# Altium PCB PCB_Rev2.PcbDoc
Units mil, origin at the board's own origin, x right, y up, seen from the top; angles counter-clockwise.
Board outline 1399.86 x 1600.52 mil, 2 copper layers (Top Layer, Bottom Layer), stack 61.2 mil thick; 31 components, 28 nets, 195 pads, 54 vias.
Unrouted connection lines stored in the file: 15.
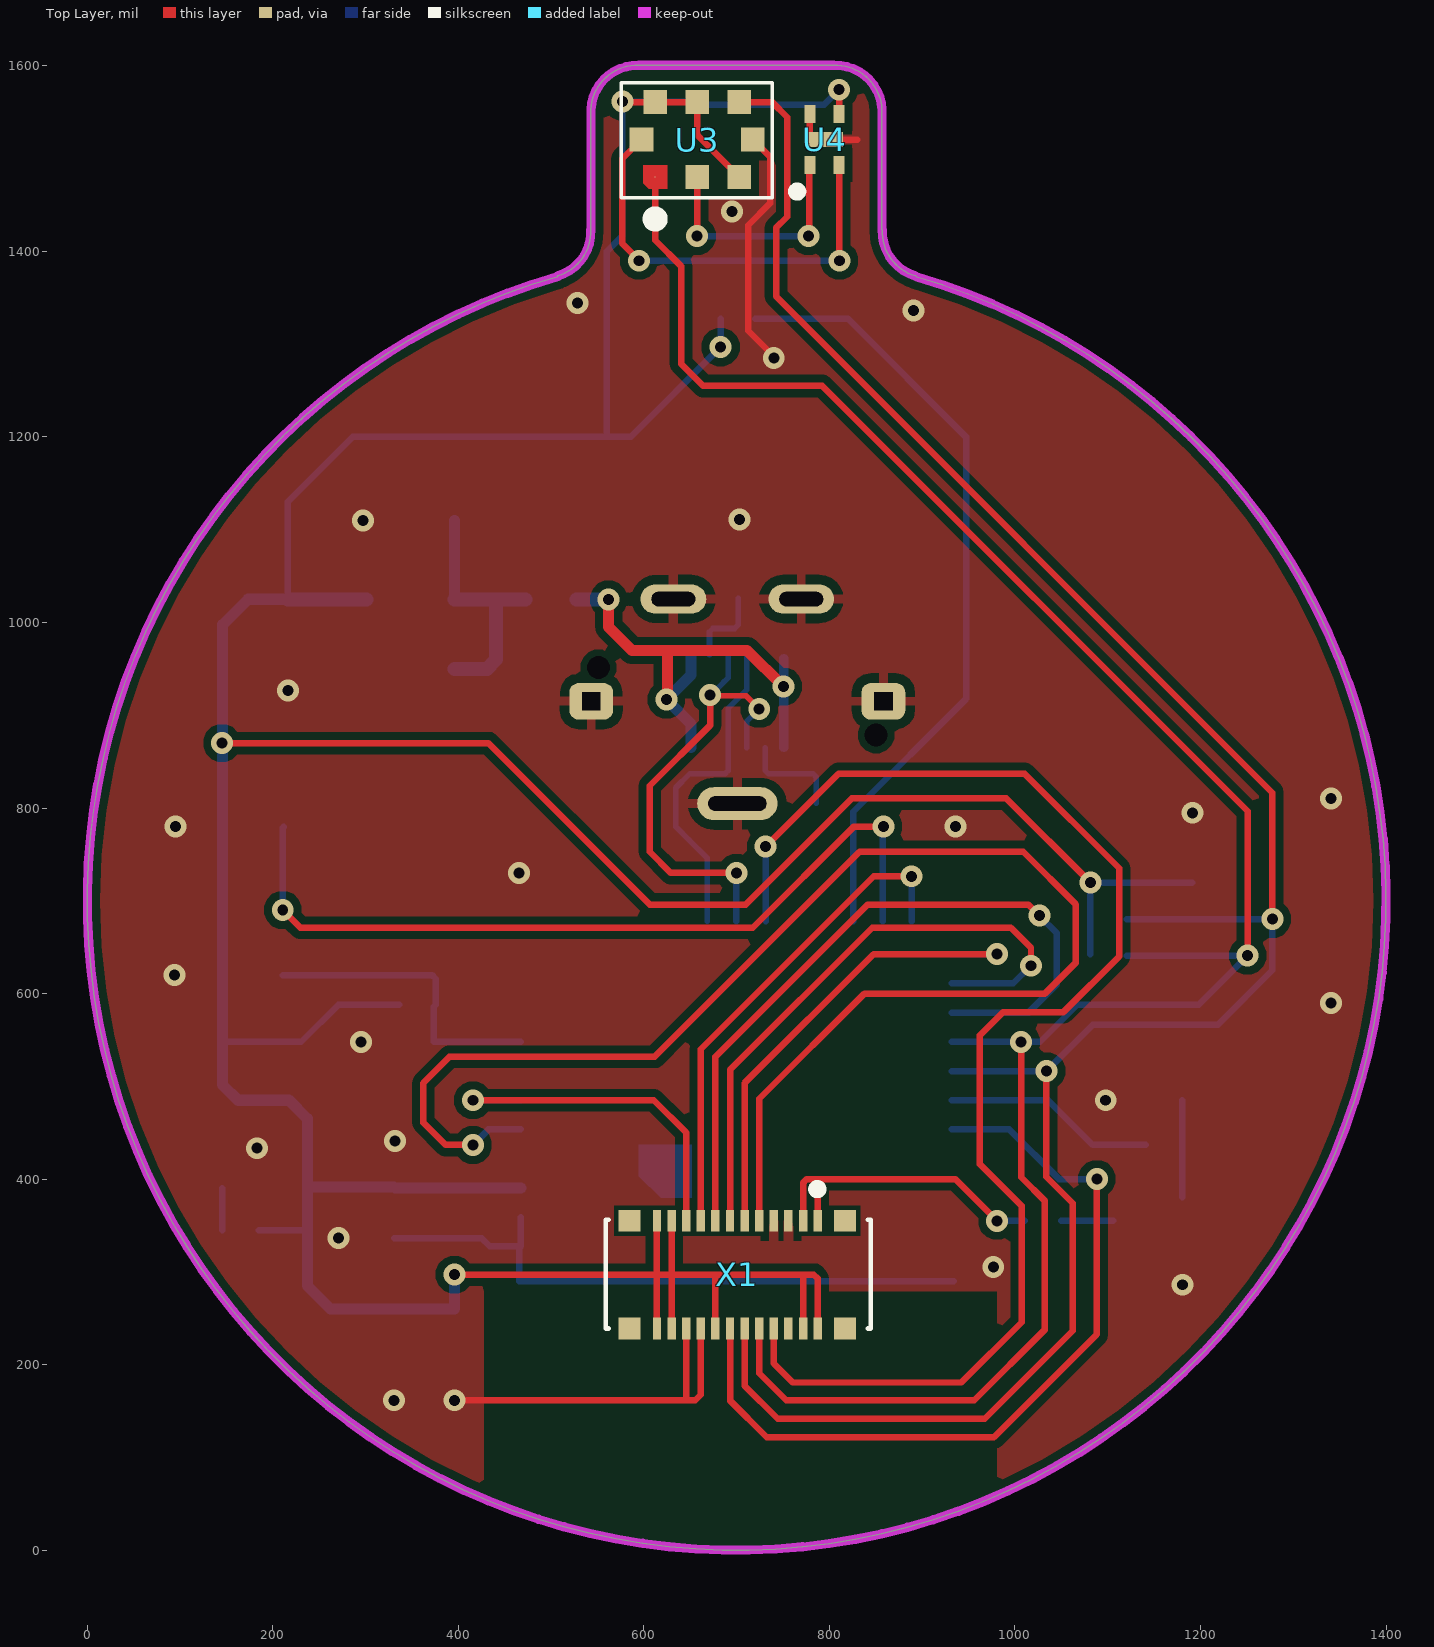
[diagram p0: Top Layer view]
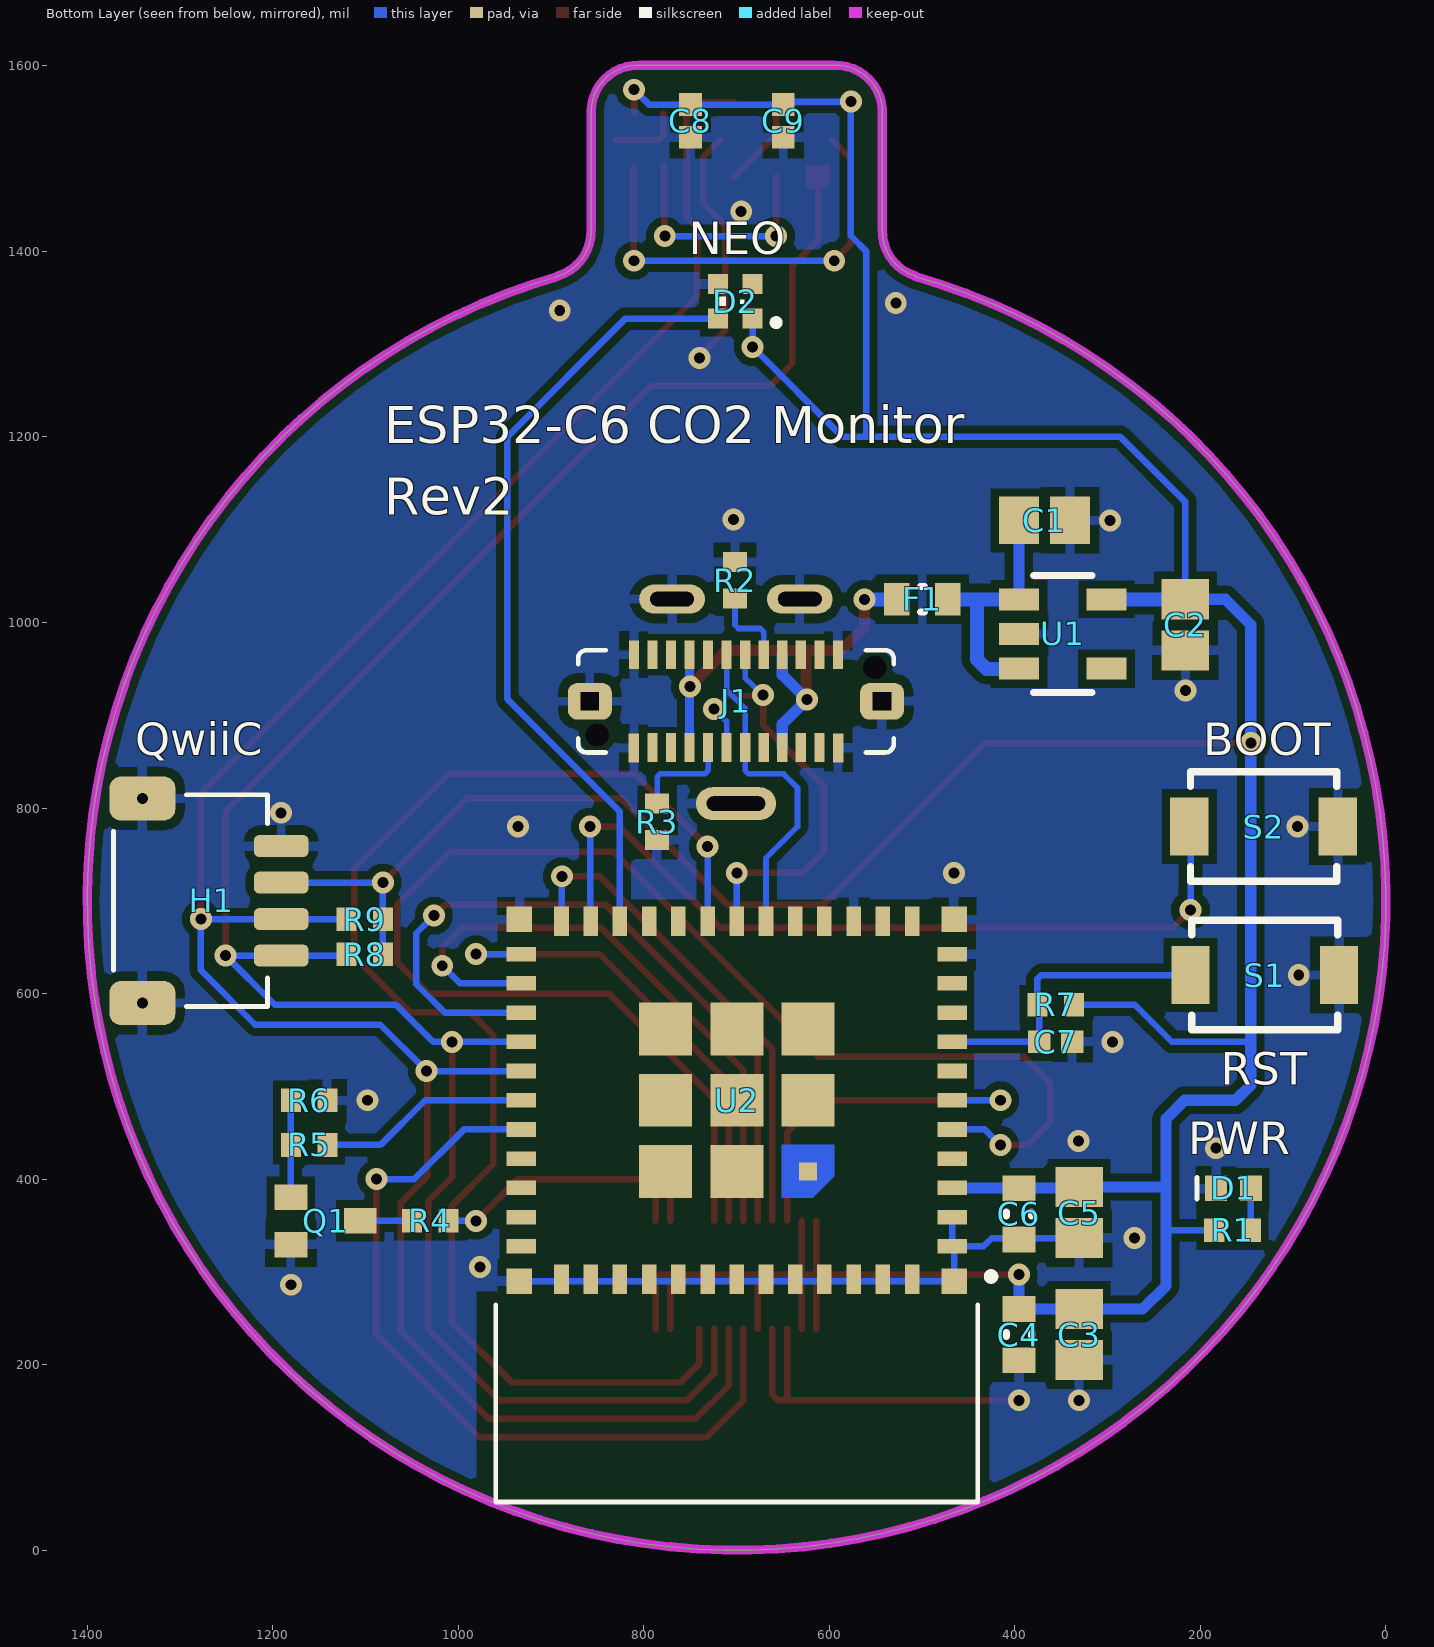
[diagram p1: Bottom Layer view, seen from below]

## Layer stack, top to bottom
Top Solder: solder mask 0.4, Solder Resist, Dk 3.5
Top Layer: signal copper 1.4
Dielectric 1: dielectric 58.4, FR-4, Dk 4.8
Bottom Layer: signal copper 1.4
Bottom Solder: solder mask 0.4, Solder Resist, Dk 3.5

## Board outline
506.96,1373.65 ccw(c492.74,1421.59) 542.7,1423.52 542.79,1423.52 542.79,1552.62 cw(c592.75,1550.69) 594.69,1600.65 804.69,1600.65 cw(c806.62,1550.69) 856.59,1552.62 856.59,1423.52 856.86,1423.52 ccw(c906.82,1421.59) 892.6,1373.65 894.4,1372.44 cw(c699.93,700)

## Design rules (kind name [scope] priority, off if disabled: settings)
Clearance Clearance_X1 [InComponent('X1')] p1: gap=5 ignorepadtopadclearanceinfootprint=FALSE
Clearance Clearance_U2 [All vs InComponent('U2')] p2: gap=8 ignorepadtopadclearanceinfootprint=FALSE
Clearance Clearance_J1 [All vs InComponent('J1')] p3: gap=7 ignorepadtopadclearanceinfootprint=FALSE
Clearance [All] p4: gap=8.7 ignorepadtopadclearanceinfootprint=FALSE
HoleSize [All] p1: absolutevalues=TRUE maxlimit=200 minlimit=1 maxpercent=80.000 minpercent=20.000
MinimumSolderMaskSliver MinimumSolderMaskSliver_X1 [All vs InComponent('X1')] p1: minsoldermaskwidth=0.6
MinimumSolderMaskSliver [All] p2: minsoldermaskwidth=0.6
NetAntennae [All] p1 off: netantennaetolerance=0
PlaneConnect [All] p1: planeconnectstyle=Direct reliefexpansion=20 reliefentries=4 reliefconductorwidth=10 reliefairgap=10
PolygonConnect PolygonConnect_Via [(IsVia)] p1: connectstyle=Direct reliefconductorwidth=10 reliefentries=4 polygonreliefangle="90 Angle" airgapwidth=10
PolygonConnect [All] p2: connectstyle=Relief reliefconductorwidth=10 reliefentries=4 polygonreliefangle="90 Angle" airgapwidth=10
RoutingVias [All] p1: holewidth=11.81 width=23.62 viastyle="Through Hole" minholewidth=11.81 minwidth=23.62 maxholewidth=11.81 maxwidth=23.62
SilkToSilkClearance [All] p1: silktosilkclearance=5
SilkToSolderMaskClearance [IsPad] p1: minsilkscreentomaskgap=5 clearancetoexposedcopper=TRUE
SolderMaskExpansion [All] p1: expansion=4 istentingtop=FALSE
SupplyNets "Schematic Supply Nets_3" [InNet('GND')] p1: voltage=0.000
SupplyNets "Schematic Supply Nets_2" [InNet('+3.3V')] p2: voltage=0.000
Width [All] p1: maxlimit=40 minlimit=6 preferedwidth=7
24 further rules are at their usual default settings.

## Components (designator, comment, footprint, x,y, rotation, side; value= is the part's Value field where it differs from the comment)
C1 "10uF" CAPC2012X140N 368.12,1110.04 r180 bottom
C2 "10uF" CAPC2012X140N 216.19,997.48 r270 bottom
C3 "10uF" CAPC2012X140N 330.68,232.48 r270 bottom
C4 "0.1uF" CAPC1608X09L 395.68,232.48 r270 bottom
C5 "10uF" CAPC2012X140N 330.68,363.98 r270 bottom
C6 "0.1uF" CAPC1608X09L 395.68,362.48 r270 bottom
C7 "1uF" CAPC1005X56N 355.96,548.04 r180 bottom
C8 "0.1uF" CAPC1005X56N 749.69,1540.65 r270 bottom
C9 "0.1uF" CAPC1005X56N 649.69,1540.65 r270 bottom
D1 "Green Led" LED1005X40N-Green 164.38,390.04 r180 bottom
D2 "RGB" SK6805-EC14 701.38,1346.34 r0 bottom value=NeoPixel
F1 "PTC" "RESC1608X06L (0603 FOOTPRINT)" 499.82,1025.04 r0 bottom
H1 "QWiiC" HC-1.0-4PWT-B-HW 1265.68,700.04 r270 bottom
J1 "USB-C VERT" GT-USB-8018B 700.68,915.04 r180 bottom locked
Q1 "MMST3904" SC-70 1143.08,355.04 r180 bottom
R1 "27K" "RESC1005X40L (0402 FOOTPRINT)" 165.36,345.04 r0 bottom
R2 "5.1K" "RESC1005X40L (0402 FOOTPRINT)" 701.68,1045.73 r270 bottom
R3 "5.1K" "RESC1005X40L (0402 FOOTPRINT)" 785.68,785.36 r90 bottom
R4 "10R" "RESC1005X40L (0402 FOOTPRINT)" 1030.36,355.04 r0 bottom
R5 "1K" "RESC1005X40L (0402 FOOTPRINT)" 1160.8,436.82 r180 bottom
R6 "10K" "RESC1005X40L (0402 FOOTPRINT)" 1160.8,485.04 r180 bottom
R7 "10K" "RESC1005X40L (0402 FOOTPRINT)" 355.99,588.04 r180 bottom
R8 "2K" "RESC1005X40L (0402 FOOTPRINT)" 1100.99,642.52 r0 bottom
R9 "2K" "RESC1005X40L (0402 FOOTPRINT)" 1100.99,680.04 r0 bottom
S1 "=Value" TL1015AF160QG 130.68,620.04 r180 bottom
S2 "=Value" TL1015AF160QG 131.94,780.04 r180 bottom
U1 "RT9080-33GJ5" SOT95P280X144-5N 348.44,987.64 r180 bottom
U2 "ESP32-C6 MINI" ESP32-C6-MINI-1 699.78,485.04 r0 bottom locked value=ESP32-C6-MINI-1-N4
U3 "STCC4" STCC4 657.39,1520.65 r90 top
U4 "SHT40" "DFN-4 (1.5mm X 1.5mm)" 794.69,1520.65 r90 top
X1 "LCD Connector" BM10NB(0.8)-24DS-0.4V(51) 700.68,297.04 r270 top

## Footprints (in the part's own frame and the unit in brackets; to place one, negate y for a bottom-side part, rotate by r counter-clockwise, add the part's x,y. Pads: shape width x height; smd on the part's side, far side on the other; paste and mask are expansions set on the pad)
BM10NB(0.8)-24DS-0.4V(51) [mm] "CONN RCPT 24POS SMD GOLD"
  rect 0.6x0.23 smd: 1(-1.475,2.2) 2(-1.475,1.8) 3(-1.475,1.4) 4(-1.475,1) 5(-1.475,0.6) 6(-1.475,0.2) 7(-1.475,-0.2) 8(-1.475,-0.6) 9(-1.475,-1) 10(-1.475,-1.4) 11(-1.475,-1.8) 12(-1.475,-2.2) 13(1.475,-2.2) 14(1.475,-1.8) 15(1.475,-1.4) 16(1.475,-1) 17(1.475,-0.6) 18(1.475,-0.2) 19(1.475,0.2) 20(1.475,0.6) 21(1.475,1) 22(1.475,1.4) 23(1.475,1.8) 24(1.475,2.2)
  rect 0.6x0.6 smd: ""(-1.475,2.95) ""(-1.475,-2.95) ""(1.475,2.95) ""(1.475,-2.95)
  silkscreen extent -2.47,-3.6 1.48,3.65, body extent -1.49,-3.6 1.49,3.6, height 0.8
CAPC1005X56N [mm] "Chip Capacitor, 2-Leads, Body 1.0x0.5mm, IPC Medium Density (0402 ceramic)"
  rect 0.62x0.62 smd: 1(-0.45,0) 2(0.45,0)
  body extent -0.55,-0.3 0.55,0.3, height 0.6
CAPC1608X09L [mm] "Chip Capacitor, 2-Leads, Body 1.6x0.8mm, IPC High Density (0603 dense)"
  rect 0.7x0.9 smd: 1(-0.7,0) 2(0.7,0)
  silkscreen extent -0.05,-0.35 0.05,0.35, body extent -0.89,-0.48 0.88,0.48, height 1.03
CAPC2012X140N [mm] "Chip Capacitor, 2-Leads, Body 2.0x1.3mm, IPC Medium Density (0805 ceramic)"
  rect 1.1x1.3 smd: 1(-0.7,0) 2(0.7,0)
  body extent -1,-0.62 1,0.63, height 1.24
"DFN-4 (1.5mm X 1.5mm)" [mm] "DFN-4 (1.5mm X 1.5mm)"
  rect 0.5x0.3 smd mask+0.076: 1(-0.7,0.4) 2(-0.7,-0.4) 3(0.7,-0.4) 4(0.7,0.4)
  rect 0.4x1 smd mask+0.076: ""(0,0)
  silkscreen extent -1.55,0.63 -1.3,0.87, body extent -0.76,-0.75 0.76,0.75, height 0.54
ESP32-C6-MINI-1 [mm] "Bluetooth, WiFi Transceiver Module 2.4GHz PCB Trace,SMD"
  rect 0.8x0.4 smd: 1(-5.9,4) 2(-5.9,3.2) 3(-5.9,2.4) 4(-5.9,1.6) 5(-5.9,0.8) 6(-5.9,0) 7(-5.9,-0.8) 8(-5.9,-1.6) 9(-5.9,-2.4) 10(-5.9,-3.2) 11(-5.9,-4) 25(5.9,-4) 26(5.9,-3.2) 27(5.9,-2.4) 28(5.9,-1.6) 29(5.9,-0.8) 30(5.9,0) 31(5.9,0.8) 32(5.9,1.6) 33(5.9,2.4) 34(5.9,3.2) 35(5.9,4)
  rect 0.4x0.8 smd: 12(-4.8,-4.9) 13(-4,-4.9) 14(-3.2,-4.9) 15(-2.4,-4.9) 16(-1.6,-4.9) 17(-0.8,-4.9) 18(0,-4.9) 19(0.8,-4.9) 20(1.6,-4.9) 21(2.4,-4.9) 22(3.2,-4.9) 23(4,-4.9) 24(4.8,-4.9) 36(4.8,4.9) 37(4,4.9) 38(3.2,4.9) 39(2.4,4.9) 40(1.6,4.9) 41(0.8,4.9) 42(0,4.9) 43(-0.8,4.9) 44(-1.6,4.9) 45(-2.4,4.9) 46(-3.2,4.9) 47(-4,4.9) 48(-4.8,4.9)
  rect 1.45x1.45 smd: 49(0,0) ""(-1.95,-1.95) ""(-1.95,0) ""(0,-1.95) ""(0,1.95) ""(1.95,-1.95) ""(1.95,0) ""(1.95,1.95)
  rect 0.7x0.7 smd: 50(5.95,4.95) 51(5.95,-4.95) 52(-5.95,-4.95) 53(-5.95,4.95)
  rect 0.5x0.5 smd paste-1 mask+0: ""(-1.95,1.95)
  Top Layer region: -1.225,1.225 -2.675,1.225 -2.675,2.075 -2.075,2.675 -1.225,2.675
  silkscreen extent -7.06,4.73 6.6,11, body extent -6.6,-5.63 6.6,10.97, height 2.55
GT-USB-8018B [mm] "USB-C Connector Vert w/TH Mount"
  round 0 hole 0.635 unplated: 1(-3.8,-0.925) 1(3.8,0.925)
  rect 0.279x0.79 smd: A1(2.793,1.275) A2(2.285,1.275) A3(1.777,1.275) A4(1.269,1.275) A5(0.761,1.275) A6(0.253,1.275) A7(-0.255,1.275) A8(-0.763,1.275) A9(-1.271,1.275) A10(-1.779,1.275) A11(-2.287,1.275) A12(-2.795,1.275) B1(-2.8,-1.275) B2(-2.287,-1.265) B3(-1.779,-1.265) B4(-1.271,-1.265) B5(-0.763,-1.265) B6(-0.255,-1.265) B7(0.253,-1.265) B8(0.761,-1.265) B9(1.269,-1.265) B10(1.777,-1.265) B11(2.285,-1.265) B12(2.8,-1.275)
  rrect50% 1.2x1 hole 0.5 square: TAB(-4,0) TAB(4,0)
  oval 1.8x0.8 hole 0.4 slot 1.2 at 0 deg: TAB(-1.75,2.8) TAB(1.75,2.8)
  oval 2.2x0.9 hole 0.4 slot 1.6 at 0 deg: TAB(0,-2.8)
  silkscreen extent -4.32,-1.4 4.32,1.4, body extent -4.32,-1.4 4.33,1.4, height 11.2
HC-1.0-4PWT-B-HW [mm] "CONN HEADER 4POS .100 R/A QWIIC"
  rrect50% 0.6x1.5 smd: 1(1.5,1.9) 2(0.5,1.9) 3(-0.5,1.9) 4(-1.5,1.9)
  rrect50% 1.2x1.8 smd: 5(-2.8,-1.9) 5(2.8,-1.9)
  silkscreen extent -2.9,-2.69 2.9,1.52, body extent -3,-2.69 3,2.26, height 3.25
LED1005X40N-Green [mm] "Chip LED 2-Leads, Body 1.0x0.5mm, (0402)"
  rect 0.6x0.7 smd: 1(-0.475,0) 2(0.475,0)
  silkscreen extent -1,-0.3 -1,0.3, body extent -0.5,-0.3 0.5,0.3, height 0.2
"RESC1005X40L (0402 FOOTPRINT)" [mm] "Chip Resistor, 2-Leads, Body 1.0x0.5mm, IPC Medium Density (0402)"
  rect 0.55x0.65 smd: 1(-0.5,0) 2(0.5,0)
  body extent -0.57,-0.27 0.58,0.28, height 0.41
"RESC1608X06L (0603 FOOTPRINT)" [mm] "Chip Resistor, 2-Leads, Body 1.6x0.8mm, IPC High Density (0603 dense)"
  rect 0.7x0.9 smd: 1(-0.7,0) 2(0.7,0)
  silkscreen extent -0.05,-0.35 0.05,0.35, body extent -0.85,-0.4 0.85,0.4, height 0.56
SC-70 [mm] "SOT23, 3-Leads, Body 2x1.25mm, Pitch 0.65mm"
  rect 0.9x0.7 smd: 1(-0.95,0.65) 2(-0.95,-0.65) 3(0.95,0)
  body extent -1.2,-1.1 1.2,1.1, height 1
SK6805-EC14 [mm] "NeoPixel 1.4mm x 1.4mm"
  rect 0.55x0.55 smd: 1(-0.475,0.475) 2(-0.475,-0.475) 3(0.475,-0.475) 4(0.475,0.475)
  silkscreen extent -1.19,-0.13 0.51,0.66, body extent -0.7,-0.7 0.7,0.7, height 0.65
SOT95P280X144-5N [mm] "SOT23, 5-Leads, Body 3.1x3.0mm (max), Pitch 0.95mm, IPC Medium Density (RFMD SOT23-5)"
  rect 1.1x0.6 smd: 1(-1.2,0.95) 2(-1.2,0) 3(-1.2,-0.95) 4(1.2,-0.95) 5(1.2,0.95)
  silkscreen extent -0.8,-1.6 0.8,1.6, body extent -1.4,-1.45 1.4,1.45, height 1.45
STCC4 [mm] "STCC4, 8-Pins"
  round 0.025 smd: 1(-1.025,1.15)
  rect 0.65x0.65 smd: 2(-1.025,0) 3(-1.025,-1.15) 4(0,-1.525) 5(1.025,-1.15) 6(1.025,0) 7(1.025,1.15) 8(0,1.525)
  Top Layer region: -1.2,1.475 -0.7,1.475 -0.7,0.825 -1.35,0.825 -1.35,1.325
  silkscreen extent -2.33,-2.06 1.56,2.08, body extent -1.5,-2 1.5,2, height 1.22
TL1015AF160QG [mm] "SWITCH TACTILE SPST-NO 0.05A 12V"
  rect 1.05x1.59 smd: 1(-2.032,0) 2(2.032,0)
  silkscreen extent -2,-1.5 2,1.5, body extent -2.3,-1.5 2.3,1.5, height 2

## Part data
C1 C2 C5: library part CAP_0805, "CAP 10uF 50V 0805"
C3: library part CAP_0805, "CAP 10uF 0805"
C4 C6: library part CAP_0603, "CAP 0.1uF 0603"
C7: library part CAP_0402, "CAP 1uF 0402"
C8 C9: library part CAP_0402, "CAP 0.1uF 0402"
D1: library part LED_0402_SMALL_GREEN, "LED Green 0402"
D2: library part SK6805-EC14, "LED,RGB,NEOPIXEL,SK6805-EC14", Manufacturer=OPSCO
F1: library part PTC_FUSE_0603, "PTC FUSE 0.5mA hold, 1A trip 0603", Manufacturer="JDT Fuse"
H1: library part HC-1.0-4PWT-B-HW, "CONN HEADER 4POS .100 R/A QWIIC", LCSC_Part_Number=C19270571, Manufacturer=HCTL
J1: library part USB-C_VERT_TH_MOUNT_RIDGID, "CONN RECPT USB-C Vertical w/TH Mount", Manufacturer=G-Switch
Q1: "TRANSISTOR NPN GP 40V SC-70", Manufacturer=Changjiang
R1: library part RES_0402, "RES 27K 0402"
R2 R3: library part RES_0402, "RES 5.1K 0402"
R4: library part RES_0402, "RES 10R 0402"
R5: library part RES_0402, "RES 1K 0402"
R6 R7: library part RES_0402, "RES 10K 0402"
R8 R9: library part RES_0402, "RES 2K 0402"
S1 S2: library part TL1015AF160QG, "SWITCH MOMENTARY"
U1: "IC LDO 3.3V 0.6A SOT23-5", Manufacturer="Richtek Tech"
U2: library part ESP32-C6-MINI-1-N4, "WIFI/Bluetooth, 4M Flash  QFN-56 7x7", Manufacturer=Espressif
U3: "CO2 SENSOR I2C SMD", Manufacturer=Sensirion
U4: "Sensor Humidity/Temperature I2C SMD", Manufacturer="Sensirion AG"
X1: library part "FFC, FPC 24 pin 0.5mm Con 1.28\" TFT", "FFC, FPC 24 pin 0.4mm Connector for 1.28\" TFT", Manufacturer=Hirose

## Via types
v1: diameter 23.62, hole 11.81, Top Layer to Bottom Layer, tented both sides, 54 vias

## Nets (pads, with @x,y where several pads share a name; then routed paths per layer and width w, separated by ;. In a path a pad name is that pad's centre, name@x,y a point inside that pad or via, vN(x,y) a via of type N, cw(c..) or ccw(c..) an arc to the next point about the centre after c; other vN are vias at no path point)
+3.3V: C2.1 C3.1 C4.1 C5.1 C6.1 C8.1 C9.1 D2.1 H1.3 R1.2 R7.2 R8.1 R9.1 U1.5 U2.3 U3.3 U3.6 U3.7 U4.3 X1.11 X1.12 X1.13 X1.14 X1.17 X1.23 X1.24 | length 5207.8
  Top Layer w7: v1(145.26,870.04) 432.26,870.04 606.28,696.03 709.73,696.03 824.02,810.32 990.72,810.32 v1(1081.31,719.73) ; v1(395.68,297.04) 614.07,297.04 ; v1@577.39,1561.01 U3.7 U3.6 657.39,1525.57 U3.3 ; X1.13 614.07,297.04 ; X1.12 614.07,297.04 ; X1.14 629.81,297.04 ; X1.11 629.81,297.04 ; X1.17 677.06,297.04 ; X1.23 771.55,297.04 ; X1.24 787.29,292.94 783.19,297.04 771.55,297.04 ; U4.3 v1(810.44,1574.34) ; 614.07,297.04 629.81,297.04 ; 629.81,297.04 677.06,297.04 ; 677.06,297.04 771.55,297.04
  Bottom Layer w7: 145.68,548.04 230.76,548.04 270.77,588.04 R7.2 ; R1.2 237.26,345.04 ; C2.1 216.19,1130.04 286.19,1200.04 560,1200.04 ; C5.1 C5.1@331.66,390.56 ; D2.1 v1(682.68,1296.9) 585.82,1200.04 560,1200.04 ; v1(810.44,1574.34) 794.47,1558.37 C8.1 C9.1 646.56,1561.49 v1(576.8,1561.49) 576.8,1416.8 560,1400 560,1200.04 ; R8.1 R9.1 v1(1081.31,719.73) H1.3
  Bottom Layer w12: C2.1 173.16,1025.04 145.68,997.56 145.68,548.04 145.68,501.62 162.26,485.04 217.26,485.04 237.26,465.04 237.26,391.54 ; C5.1 237.26,391.54 ; C5.1@331.66,390.56 U2.3 ; v1(395.68,297.04) C4.1 C3.1 262.26,260.04 237.26,285.04 237.26,345.04 237.26,391.54
  Bottom Layer w15: C2.1 U1.5
C_INT: U2.19 X1.21 | length 1484.7
  Top Layer w7: v1(731.28,758.54) 809.77,837.04 1010.26,837.04 1112.26,735.04 1112.26,640.04 1052.26,580.04 987.26,580.04 962.26,555.04 962.26,416.06 1007.26,371.06 1007.26,245.85 942.2,180.79 760.55,180.79 740.05,201.29 X1.21
  Bottom Layer w7: U2.19 v1(731.28,758.54)
C_RST: U2.31 X1.18 | length 881.3
  Top Layer w7: X1.18 692.81,161.28 732.43,121.65 977.29,121.65 1088.26,232.62 v1(1088.26,400.04)
  Bottom Layer w7: U2.31 993.91,453.55 1047.41,400.04 v1(1088.26,400.04)
D+: J1.A6 J1.B6 U2.18 | length 507.3
  Top Layer w6: v1@672.3,920.91 710.3,920.91 v1(724.3,906.91)
  Top Layer w7: v1(671.3,921.91) 671.3,889.09 606.28,824.06 606.28,752.83 629.07,730.04 v1(699.78,730.04)
  Bottom Layer w6: v1@672.07,921.91 686.26,936.1 ; 686.52,936.1 690.76,940.34 J1.A6@690.76,965.44 ; J1.B6 710.72,893.33 v1(724.3,906.91)
  Bottom Layer w7: U2.18 v1(699.78,730.04)
D-: J1.A7 J1.B7 U2.17 | length 355.5
  Bottom Layer w6: U2.17 668.28,746.06 649.3,765.04 634.3,780.04 634.3,821.91 649.3,836.91 687.25,836.91 690.76,840.43 J1.B7@690.76,865.24 ; J1.B7 690.72,907.33 710.76,927.37 J1.A7@710.76,965.44
EN: C7.1 R7.1 S1.1 U2.8 | length 326.4
  Bottom Layer w7: S1.1 371.58,620.04 375.68,615.94 R7.1 ; R7.1@373.68,586.04 C7.1 U2.8
GND: C1.2 C2.2 C3.2 C4.2 C5.2 C6.2 C7.2 C8.2 C9.2 D1.1 D2.3 H1.4 H1.5 J1.A1 J1.A12 J1.B1 J1.B12 J1.TAB Q1.2 R2.1 R3.1 R6.2 S1.2 S2.2 U1.2 U2.1 U2.2 U2.11 U2.14 U2.36 U2.37 U2.38 U2.39 U2.40 U2.41 U2.42 U2.43 U2.44 U2.45 U2.46 U2.47 U2.48 U2.50 U2.51 U2.52 U2.53 U3.4 U4. U4.4 X1.3 X1.4 X1.15 X1.16 | length 1436.5
  Top Layer w7: v1(395.68,161.62) 644.69,161.62 ; X1.15 645.56,162.49 644.69,161.62 ; X1.16 661.31,167.61 655.32,161.62 644.69,161.62 ; U3.4 735.92,1502.16 735.92,1451.86 712.39,1428.33 712.39,1314.52 740,1286.91 v1(740,1285) ; U4.4 778.94,1525.03 783.31,1520.65 830.07,1520.65
  Bottom Layer w7: C5.2 425.03,336.42 433.89,327.56 U2.1 ; U2.2 U2.1 ; U2.50 U2.53 465.53,325.59 U2.1
  other v1: 330.68,161.62 1180.48,286.15 976.6,305.15 270.84,336.42 183.08,433.35 331.54,440.9 1097.81,485.04 294.94,548.04 1340.48,589.81 93.98,620.04 465.53,730.04 95.24,780.04 935.68,780.04 1191.16,794.92 1340.48,810.28 216.19,926.62 297.26,1110.04 703.19,1111.25 890.63,1336.44 528.39,1344.22 695,1443
IO9: S2.1 U2.23 | length 893.5
  Top Layer w7: v1(210.68,690.04) 229.7,671.03 717.33,671.03 826.34,780.04 v1(858.16,780.04)
  Bottom Layer w7: v1(210.68,690.04) 210.68,778.78 S2.1 ; U2.23 857.71,678.41 857.71,779.59 v1(858.16,780.04)
LCD_BL: R5.2 U2.30 | length 229
  Bottom Layer w7: U2.30 1035.68,485.04 1083.91,436.82 R5.2
NEO: D2.4 U2.22 | length 852.4
  Bottom Layer w7: D2.4 819.66,1327.64 947.26,1200.04 947.26,917.58 825.76,796.08 U2.22
NetC1_1: C1.1 F1.1 U1.1 U1.3 | length 275.8
  Bottom Layer w7: U1.3 U1.3@395.88,950.04
  Bottom Layer w12: U1.1 C1.1
  Bottom Layer w15: U1.1 440.68,1025.04 ; U1.3@395.88,950.04 430.68,950.04 440.68,960.04 440.68,1025.04 ; F1.1 440.68,1025.04
NetD1_2: D1.2 R1.1 | length 45
  Bottom Layer w7: R1.1 D1.2
NetF1_2: F1.2 J1.A4 J1.A9 J1.B4 J1.B9 | length 551.2
  Top Layer w12: v1(562.02,1025.04) 562.02,995.28 587.39,969.91 625.3,969.91 ; v1@625.3,915.91 625.3,969.91 ; v1@751.3,929.91 v1(750.3,930.91) 711.3,969.91 625.3,969.91
  Bottom Layer w10: J1.B4 J1.A9@750.72,961.16
  Bottom Layer w12: v1(624.3,916.91) 650.72,943.33 J1.A4 ; v1@625.3,915.91 650.72,890.49 J1.B9
  Bottom Layer w15: F1.2 v1(562.02,1025.04)
NetJ1_A5: J1.A5 R2.2 | length 87.1
  Bottom Layer w6: J1.A5 670.72,989.99 674.3,993.57 698.06,993.57 ; 698.06,993.94 701.64,997.52 ; 701.68,997.56 R2.2
NetJ1_B5: J1.B5 R3.2 | length 110.9
  Bottom Layer w6: J1.B5 730.72,840.49 734.3,836.91 782.06,836.91 ; 782.06,837.15 785.64,833.56 ; R3.2@785.68,805.28 785.68,833.52
NetQ1_1: Q1.1 R5.1 R6.1 | length 104.4
  Bottom Layer w7: Q1.1 R5.1 R6.1
NetQ1_3: Q1.3 R4.2 | length 55.6
  Bottom Layer w7: R4.2 Q1.3
NetR4_1: R4.1 X1.1 X1.2 | length 345.2
  Top Layer w7: X1.2 771.55,395.94 775.65,400.04 787.29,400.04 ; X1.1 787.29,400.04 ; v1(980.68,355.04) 935.68,400.04 787.29,400.04
  Bottom Layer w7: v1(980.68,355.04) R4.1
NetU3_2: U3.2 U4.1 | length 260.7
  Top Layer w7: v1(657.39,1416.65) U3.2 ; v1(777.39,1416.65) 778.16,1417.43 778.16,1492.32 U4.1
  Bottom Layer w7: v1(657.39,1416.65) v1(777.39,1416.65)
NetU3_8: U3.8 U4.2 | length 463.4
  Top Layer w7: v1(594.69,1390) 594.69,1390.65 576.76,1408.58 576.76,1500.07 U3.8 ; v1(810.72,1390) 810.58,1390.14 810.58,1490.5 U4.2@810.72,1490.64
  Bottom Layer w7: v1(594.69,1390) v1(810.72,1390)
SCL: H1.1 R8.2 U2.28 U3.1 X1.20 | length 2387
  Top Layer w7: U3.1 612.11,1412.19 640,1384.3 640,1279.04 664.04,1255 792.33,1255 1250.82,796.51 v1(1250.82,640.99) ; X1.20 724.3,190.79 753.47,161.62 956.01,161.62 1032.26,237.87 1032.26,376.46 1006.68,402.04 v1(1006.68,548.04)
  Bottom Layer w7: U2.28 v1(1006.68,548.04) 1027.18,548.04 1067.19,588.04 1197.87,588.04 v1(1250.82,640.99) H1.1 1120.73,640.99 R8.2@1120.68,641.04
SDA: H1.2 R9.2 U2.29 U3.5 X1.19 | length 2512.7
  Top Layer w7: U3.5 738.05,1561.01 754.43,1544.63 754.43,1437.49 742.39,1425.45 742.39,1351.69 1277.43,816.65 v1(1277.43,680.36) ; X1.19 708.55,177.37 744.27,141.65 967.43,141.65 1062.26,236.48 1062.26,374.04 1033.68,402.62 v1@1033.68,516.04
  Bottom Layer w7: U2.29 1034.05,516.54 1084.06,566.55 1218.87,566.55 1277.43,625.11 v1(1277.43,680.36) H1.2 1120.99,680.36 R9.2
  other v1: 1034.05,516.36
SPI_CLK: U2.27 X1.8 | length 806.5
  Top Layer w7: X1.8 677.06,531.8 841.29,696.03 1014.28,696.03 v1(1026.26,684.04)
  Bottom Layer w7: U2.27 1014.58,579.53 1045.26,610.21 1045.26,665.04 v1(1026.26,684.04)
SPI_CS: U2.24 X1.9 | length 537.8
  Top Layer w7: X1.9 661.31,540.08 847.71,726.48 v1(888.26,726.48)
  Bottom Layer w7: v1(888.26,726.48) 888.51,726.23 888.51,678.21 U2.24
SPI_MISO: U2.26 X1.7 | length 672
  Top Layer w7: X1.7 692.81,517.8 846.03,671.03 995.68,671.03 1017.26,649.45 v1(1017.26,630.04)
  Bottom Layer w7: U2.26 998.24,611.03 v1(1017.26,630.04)
SPI_MOSI: U2.25 X1.6 | length 526.7
  Top Layer w7: X1.6 708.55,503.55 847.53,642.52 v1(980.68,642.52)
  Bottom Layer w7: U2.25 v1(980.68,642.52)
TFT_DC: U2.5 X1.5 | length 1591.5
  Top Layer w7: v1(415.68,436.82) 386.28,436.82 362.06,461.03 362.06,503.55 390.31,531.8 611.42,531.8 832.45,752.83 1008.87,752.83 1065.68,696.03 1065.68,633.46 1032.26,600.04 837.82,600.04 724.3,486.52 X1.5
  Bottom Layer w7: v1(415.68,436.82) 432.41,453.55 U2.5
TFT_RST: U2.6 X1.10 | length 391.2
  Top Layer w7: v1(415.68,485.04) 610.68,485.04 645.56,450.16 X1.10
  Bottom Layer w7: v1(415.68,485.04) U2.6
pads on no net: D2.2 J1.1 J1.A2 J1.A3 J1.A8 J1.A10 J1.A11 J1.B2 J1.B3 J1.B8 J1.B10 J1.B11 U1.4 U2. U2.4 U2.7 U2.9 U2.10 U2.12 U2.13 U2.15 U2.16 U2.20 U2.21 U2.32 U2.33 U2.34 U2.35 U2.49 X1. X1.22

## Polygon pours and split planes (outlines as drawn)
GND on Top Layer "NONET_L-01_P-001" (solid, remove dead copper, pour order 4): -7.74,37.65 -7.74,-3.35 1412.26,-13.35 1412.26,1600.65 -7.74,1600.65 -7.74,67.65 -7.74,46.65
GND on Bottom Layer "NONET_L-01_P-001" (solid, remove dead copper, pour order 3): -7.74,-3.18 -7.57,-3.35 1412.26,-3.35 1412.26,1600.65 -7.74,1600.65 -7.74,66.22

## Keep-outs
Keep-Out Layer:
  lines w10: 507.05,1373.65 ccw(c492.83,1421.59) 542.79,1423.52 ; 507.25,1372.94 ccw(c700.01,700) 894.49,1372.44 ; 542.88,1423.52 542.88,1552.62 cw(c592.84,1550.69) 594.77,1600.65 804.77,1600.65 cw(c806.71,1550.69) 856.67,1552.62 856.67,1423.52 ; 856.94,1423.52 ccw(c906.91,1421.59) 892.68,1373.65

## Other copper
Top Layer:
  pour cut-out: 427.3,279.31 980.68,279.31 980.68,-35 427.3,-35
Bottom Layer:
  pour cut-out: 427.3,279.31 980.68,279.31 980.68,-35 427.3,-35
  pour cut-out: 485.43,661.65 915.85,661.65 915.85,308.65 485.43,308.65

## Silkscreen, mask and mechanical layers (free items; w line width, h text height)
Bottom Overlay:
  text "NEO" at 751.35,1397 h35
  text "ESP32-C6 CO2 Monitor" at 1079.68,1193.04 h40
  text "Rev2" at 1079.68,1116.04 h40
  text "BOOT" at 196.75,857 h35
  text "QwiiC" at 1348,857 h35
  text "RST" at 178,502 h35
  text "PWR" at 213,427 h35
Mechanical 1:
  lines w10: 506.96,1373.65 ccw(c492.74,1421.59) 542.7,1423.52 ; 507.17,1372.94 ccw(c699.93,700) 894.4,1372.44 ; 542.79,1423.52 542.79,1552.62 cw(c592.75,1550.69) 594.69,1600.65 804.69,1600.65 cw(c806.62,1550.69) 856.59,1552.62 856.59,1423.52 ; 856.86,1423.52 ccw(c906.82,1421.59) 892.6,1373.65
